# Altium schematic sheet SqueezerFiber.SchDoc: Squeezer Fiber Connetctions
size B; Organization: LIGO Laboratory; Address1: California Institute of Technology; Address2: Massachusetts Institute of Technology; SheetNumber: 30; SheetTotal: 37; DrawnBy: R.  Abbott; Engineer: R.  Abbott; PageSetup: Record=PageOptions¦CenterHorizontal=True¦CenterVertical=True¦PrintScale=1.09¦XCorrection=1.00¦YCorrection=1.00¦PrintKind=0¦BorderSize=5000000¦LeftOffset=0¦BottomOffset=0¦Orientation=2¦PaperLength=1000¦PaperWidth=1000¦Scale=100¦PaperSource=7¦PrintQuality=-4¦MediaType=1¦DitherType=10¦PaperKind=11x17¦PrintScaleMode=1
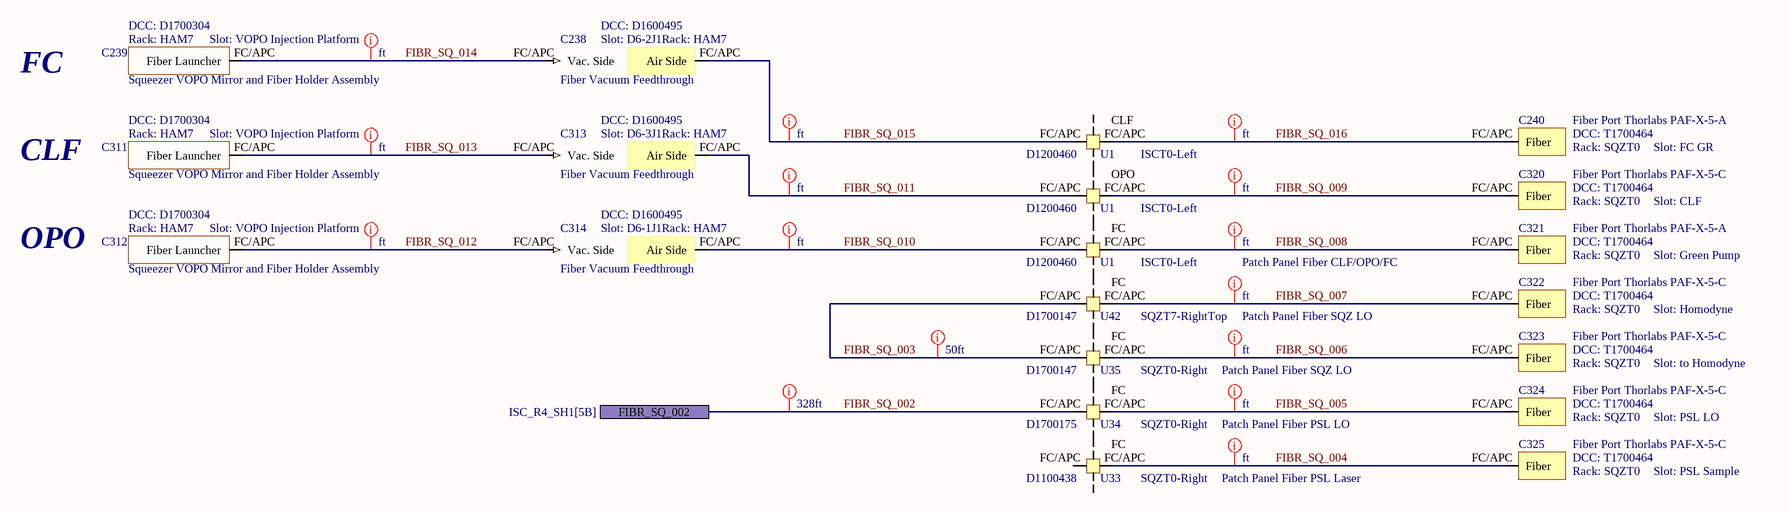
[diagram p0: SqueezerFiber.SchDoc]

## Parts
C238  Fiber Vacuum Feedthrough  DCC: D1600495  Rack: HAM7  Slot: D6-2J1
C239  Squeezer VOPO Mirror and Fiber Holder Assembly  DCC: D1700304  Rack: HAM7  Slot: VOPO Injection Platform
C240  Fiber Port Thorlabs PAF-X-5-A  DCC: T1700464  Rack: SQZT0  Slot: FC GR
C241  DCC: D1200460  Rack: ISCT0-Left  Slot: U1  (hidden comment: Patch Panel Fiber CLF/OPO/FC)  (parts A,B,C of 3)
C311  Squeezer VOPO Mirror and Fiber Holder Assembly  DCC: D1700304  Rack: HAM7  Slot: VOPO Injection Platform
C312  Squeezer VOPO Mirror and Fiber Holder Assembly  DCC: D1700304  Rack: HAM7  Slot: VOPO Injection Platform
C313  Fiber Vacuum Feedthrough  DCC: D1600495  Rack: HAM7  Slot: D6-3J1
C314  Fiber Vacuum Feedthrough  DCC: D1600495  Rack: HAM7  Slot: D6-1J1
C316  Patch Panel Fiber SQZ LO  DCC: D1700147  Rack: SQZT7-RightTop  Slot: U42
C317  Patch Panel Fiber SQZ LO  DCC: D1700147  Rack: SQZT0-Right  Slot: U35
C318  Patch Panel Fiber PSL LO  DCC: D1700175  Rack: SQZT0-Right  Slot: U34
C320  Fiber Port Thorlabs PAF-X-5-C  DCC: T1700464  Rack: SQZT0  Slot: CLF
C321  Fiber Port Thorlabs PAF-X-5-A  DCC: T1700464  Rack: SQZT0  Slot: Green Pump
C322  Fiber Port Thorlabs PAF-X-5-C  DCC: T1700464  Rack: SQZT0  Slot: Homodyne
C323  Fiber Port Thorlabs PAF-X-5-C  DCC: T1700464  Rack: SQZT0  Slot: to Homodyne
C324  Fiber Port Thorlabs PAF-X-5-C  DCC: T1700464  Rack: SQZT0  Slot: PSL LO
C325  Fiber Port Thorlabs PAF-X-5-C  DCC: T1700464  Rack: SQZT0  Slot: PSL Sample
D1100438  Patch Panel Fiber PSL Laser  DCC: D1100438  Rack: SQZT0-Right  Slot: U33

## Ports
FIBR_SQ_002 (see ISC_R4_SH1[5B])

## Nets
FIBR_SQ_002: C318.FC/APC(Fiber) ; port FIBR_SQ_002
FIBR_SQ_003: C316.FC/APC(Fiber) C317.FC/APC(Fiber)
FIBR_SQ_004: C325.FC/APC(Fiber) D1100438.FC/APC(Fiber)
FIBR_SQ_005: C318.FC/APC(Fiber) C324.FC/APC(Fiber)
FIBR_SQ_006: C317.FC/APC(Fiber) C323.FC/APC(Fiber)
FIBR_SQ_007: C316.FC/APC(Fiber) C322.FC/APC(Fiber)
FIBR_SQ_008: C241.FC/APC(OPO) C321.FC/APC(Fiber)
FIBR_SQ_009: C241.FC/APC(OPO) C320.FC/APC(Fiber)
FIBR_SQ_010: C241.FC/APC(OPO) C314.FC/APC(Air_Side)
FIBR_SQ_011: C241.FC/APC(OPO) C313.FC/APC(Air_Side)
FIBR_SQ_012: C312.FC/APC(Fiber_Launcher) C314.FC/APC(Vac._Side)
FIBR_SQ_013: C311.FC/APC(Fiber_Launcher) C313.FC/APC(Vac._Side)
FIBR_SQ_014: C238.FC/APC(Vac._Side) C239.FC/APC(Fiber_Launcher)
FIBR_SQ_015: C238.FC/APC(Air_Side) C241.FC/APC(CLF)
FIBR_SQ_016: C240.FC/APC(Fiber) C241.FC/APC(CLF)

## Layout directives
Length: 328ft: FIBR_SQ_002
Length: 50ft: FIBR_SQ_003
Length: ft: FIBR_SQ_004, FIBR_SQ_005, FIBR_SQ_006, FIBR_SQ_007, FIBR_SQ_008, FIBR_SQ_009, FIBR_SQ_010, FIBR_SQ_011, FIBR_SQ_012, FIBR_SQ_013, FIBR_SQ_014, FIBR_SQ_015, FIBR_SQ_016

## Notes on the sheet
- FC
- CLF
- OPO

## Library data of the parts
C238 C313 C314 = VacFeedFiber: Serial: Sxxxxxxx; System: ISC
C239 C311 C312 = Squeezer VOPO Mirror and Fiber Holder Assembly: Serial: Sxxxxxxx; System: ISC
C240 C320-C325 = Fiber Port Thorlabs PAF Series: Serial: Sxxxxxxx; System: ISC
C241 = Patch Panel Fiber CLF/OPO/FC: Patch Panel (D2000460); Serial: Sxxxxxxx; System: ISC
C316 C317 = Patch Panel Fiber SQZ LO: Patch Panel (D1700147); Serial: Sxxxxxxx; System: ISC
C318 = Patch Panel Fiber PSL LO: Patch Panel (D1700175); Serial: Sxxxxxxx; System: ISC
D1100438 = Patch Panel Fiber PSL Laser: Patch Panel (D1100438); Serial: Sxxxxxxx; System: ISC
